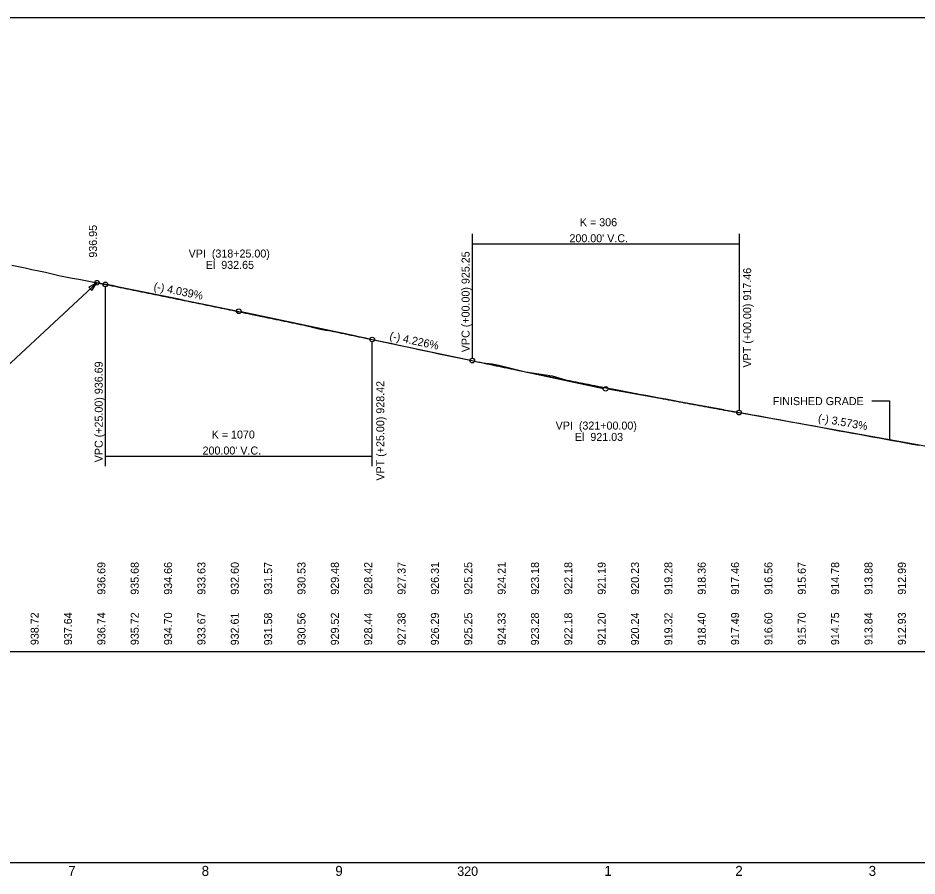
# Model space of a CAD drawing. Extents: x 4180 to 16997695, y 4 to 12629821.
# Drawn here: x 16984079 to 16984753, y 12626778 to 12627421 of the extents above; entities that cross this region are included whole.
import ezdxf

# ---------------------------------------------------------------- set-up
doc = ezdxf.new("R2010")
doc.units = 0
for name, color, linetype in [('Default', 7, 'Continuous'), ('RD_DDB_GradeTX', 7, 'Continuous'), ('RD_DDB_PI', 7, 'Continuous'), ('RD_DDB_PR_Tx', 7, 'Continuous'), ('RD_DDB_Profile_EX', 7, 'Continuous'), ('RD_DDB_Profile_PR', 7, 'Continuous'), ('RD_DDB_StaTX', 7, 'Continuous'), ('RD_DDB_StripGrade', 7, 'Continuous'), ('RD_DDB_StripGrade_PR', 7, 'Continuous'), ('RD_DDB_VCLbl', 7, 'Continuous'), ('RD_GPK_Profile_Cell', 7, 'Continuous'), ('RD_TX_Qty', 7, 'Continuous')]:
    doc.layers.add(name, color=color, linetype=linetype)

msp = doc.modelspace()

# ---------------------------------------------------------------- linework, layer by layer
at = {"layer": 'Default'}
msp.add_lwpolyline([(16983719.88, 12626945.95), (16985219.88, 12626945.95), (16985219.88, 12627420.95), (16983719.88, 12627420.95)], close=True, dxfattribs=at)
at = {"layer": 'RD_DDB_PI'}
for p, q in [((16984156.66, 12627218.86), (16984243.16, 12627201.39)), ((16984332.93, 12627182.43), (16984246.59, 12627200.68)), ((16984431.82, 12627161.54), (16984518.16, 12627143.29)), ((16984608.47, 12627127.1), (16984521.6, 12627142.62))]:
    msp.add_line(p, q, dxfattribs=at)
for centre in [(16984138.56, 12627222.51), (16984244.88, 12627201.04), (16984519.88, 12627142.93)]:
    msp.add_circle(centre, 1.75, dxfattribs=at)
at = {"layer": 'RD_DDB_PR_Tx'}
for p, q in [((16984719.29, 12627133.91), (16984732.71, 12627133.91)), ((16984732.71, 12627133.91), (16984732.71, 12627104.91))]:
    msp.add_line(p, q, dxfattribs=at)
at = {"layer": 'RD_DDB_Profile_EX'}
for points in [[(16984074.88, 12627235.61), (16984079.88, 12627234.57), (16984084.88, 12627233.52), (16984089.88, 12627232.46), (16984094.88, 12627231.4), (16984099.88, 12627230.35), (16984104.88, 12627229.19), (16984109.88, 12627227.88), (16984114.88, 12627226.94), (16984119.88, 12627226)], [(16984119.88, 12627226), (16984124.88, 12627225.06), (16984129.88, 12627224.12), (16984134.88, 12627223.19), (16984139.88, 12627222.33), (16984144.88, 12627221.49), (16984149.88, 12627220.55), (16984154.88, 12627219.34), (16984159.88, 12627218.35), (16984164.88, 12627217.37), (16984169.88, 12627216.38), (16984174.88, 12627215.38), (16984179.88, 12627214.36), (16984184.88, 12627213.34), (16984189.88, 12627212.32), (16984194.88, 12627211.31), (16984199.88, 12627210.29), (16984204.88, 12627209.26), (16984209.88, 12627208.23), (16984214.88, 12627207.19), (16984219.88, 12627206.13), (16984219.88, 12627206.13)], [(16984219.88, 12627206.13), (16984224.88, 12627205.07), (16984229.88, 12627204.02), (16984234.88, 12627202.96), (16984239.88, 12627201.9), (16984244.88, 12627200.85), (16984249.88, 12627199.8), (16984254.88, 12627198.75), (16984259.88, 12627197.7), (16984264.88, 12627196.68), (16984269.88, 12627195.67), (16984274.88, 12627194.66), (16984279.88, 12627193.65), (16984284.88, 12627192.64), (16984289.88, 12627191.62), (16984294.88, 12627190.61), (16984299.88, 12627189.26), (16984304.88, 12627187.83), (16984309.88, 12627186.84), (16984314.88, 12627186.45), (16984319.88, 12627185.39), (16984324.88, 12627184.32), (16984329.88, 12627183.25), (16984334.88, 12627182.16), (16984339.88, 12627181.07), (16984344.88, 12627179.99), (16984349.88, 12627178.93), (16984354.88, 12627177.88), (16984359.88, 12627176.82), (16984364.88, 12627175.76), (16984369.88, 12627174.68), (16984374.88, 12627173.61), (16984379.88, 12627172.53), (16984384.88, 12627171.43), (16984389.88, 12627170.34), (16984394.88, 12627169.24), (16984399.88, 12627168.18), (16984404.88, 12627167.14), (16984409.88, 12627166.11), (16984414.88, 12627165.08), (16984419.88, 12627164.04), (16984424.88, 12627162.99), (16984429.88, 12627162.21), (16984434.88, 12627161.57), (16984439.88, 12627160.72), (16984444.88, 12627159.42), (16984449.88, 12627158.12), (16984454.88, 12627156.82), (16984459.88, 12627155.61), (16984464.88, 12627154.89), (16984469.88, 12627154.18), (16984474.88, 12627153.46), (16984479.88, 12627152.61), (16984484.88, 12627151.18), (16984489.88, 12627149.7), (16984494.88, 12627148.7), (16984499.88, 12627147.72), (16984504.88, 12627146.74), (16984509.88, 12627145.76), (16984514.88, 12627144.77), (16984519.88, 12627143.78), (16984524.88, 12627142.8), (16984529.88, 12627141.81), (16984534.88, 12627140.87), (16984539.88, 12627139.92), (16984544.88, 12627138.98), (16984549.88, 12627138.06), (16984554.88, 12627137.14), (16984559.88, 12627136.23), (16984564.88, 12627135.31), (16984569.88, 12627134.37), (16984574.88, 12627133.42), (16984579.88, 12627132.48), (16984584.88, 12627131.56), (16984589.88, 12627130.66), (16984594.88, 12627129.77), (16984599.88, 12627128.87), (16984604.88, 12627127.95), (16984609.88, 12627127.03), (16984614.88, 12627126.11), (16984619.88, 12627125.23)], [(16984619.88, 12627125.23), (16984624.88, 12627124.37), (16984629.88, 12627123.52), (16984634.88, 12627122.64), (16984639.88, 12627121.71), (16984644.88, 12627120.77), (16984649.88, 12627119.84), (16984654.88, 12627118.93), (16984659.88, 12627118.05), (16984664.88, 12627117.17), (16984669.88, 12627116.29), (16984674.88, 12627115.37), (16984679.88, 12627114.41), (16984684.88, 12627113.45), (16984689.88, 12627112.48), (16984694.88, 12627111.53), (16984699.88, 12627110.63), (16984704.88, 12627109.73), (16984709.88, 12627108.83), (16984714.88, 12627107.92), (16984719.88, 12627107), (16984724.88, 12627106.07), (16984729.88, 12627105.14), (16984734.88, 12627104.23), (16984739.88, 12627103.34), (16984744.88, 12627102.44), (16984749.88, 12627101.54), (16984754.88, 12627100.66)]]:
    msp.add_lwpolyline(points, dxfattribs=at)
at = {"layer": 'RD_DDB_Profile_PR'}
for p, q in [((16984138.56, 12627222.51), (16984144.88, 12627221.24)), ((16984344.88, 12627179.91), (16984419.88, 12627164.06)), ((16984619.88, 12627125.07), (16984769.88, 12627098.27))]:
    msp.add_line(p, q, dxfattribs=at)
for points in [[(16984144.88, 12627221.24), (16984148.88, 12627220.43), (16984152.88, 12627219.62), (16984156.88, 12627218.81), (16984160.88, 12627218), (16984164.88, 12627217.19), (16984168.88, 12627216.38), (16984172.88, 12627215.56), (16984176.88, 12627214.75), (16984180.88, 12627213.94), (16984184.88, 12627213.12), (16984188.88, 12627212.31), (16984192.88, 12627211.49), (16984196.88, 12627210.67), (16984200.88, 12627209.85), (16984204.88, 12627209.04), (16984208.88, 12627208.22), (16984212.88, 12627207.4), (16984216.88, 12627206.57), (16984220.88, 12627205.75), (16984224.88, 12627204.93), (16984228.88, 12627204.11), (16984232.88, 12627203.28), (16984236.88, 12627202.46), (16984240.88, 12627201.63), (16984244.88, 12627200.81), (16984248.88, 12627199.98), (16984252.88, 12627199.15), (16984256.88, 12627198.32), (16984260.88, 12627197.49), (16984264.88, 12627196.66), (16984268.88, 12627195.83), (16984272.88, 12627195), (16984276.88, 12627194.17), (16984280.88, 12627193.34), (16984284.88, 12627192.5), (16984288.88, 12627191.67), (16984292.88, 12627190.83), (16984296.88, 12627190), (16984300.88, 12627189.16), (16984304.88, 12627188.32), (16984308.88, 12627187.49), (16984312.88, 12627186.65), (16984316.88, 12627185.81), (16984320.88, 12627184.97), (16984324.88, 12627184.13), (16984328.88, 12627183.28), (16984332.88, 12627182.44), (16984336.88, 12627181.6), (16984340.88, 12627180.75), (16984344.88, 12627179.91)], [(16984419.88, 12627164.06), (16984423.88, 12627163.22), (16984427.88, 12627162.37), (16984431.88, 12627161.54), (16984435.88, 12627160.7), (16984439.88, 12627159.87), (16984443.88, 12627159.04), (16984447.88, 12627158.21), (16984451.88, 12627157.38), (16984455.88, 12627156.56), (16984459.88, 12627155.74), (16984463.88, 12627154.92), (16984467.88, 12627154.1), (16984471.88, 12627153.29), (16984475.88, 12627152.48), (16984479.88, 12627151.68), (16984483.88, 12627150.87), (16984487.88, 12627150.07), (16984491.88, 12627149.27), (16984495.88, 12627148.47), (16984499.88, 12627147.68), (16984503.88, 12627146.89), (16984507.88, 12627146.1), (16984511.88, 12627145.31), (16984515.88, 12627144.53), (16984519.88, 12627143.75), (16984523.88, 12627142.97), (16984527.88, 12627142.19), (16984531.88, 12627141.42), (16984535.88, 12627140.65), (16984539.88, 12627139.88), (16984543.88, 12627139.11), (16984547.88, 12627138.35), (16984551.88, 12627137.59), (16984555.88, 12627136.83), (16984559.88, 12627136.08), (16984563.88, 12627135.32), (16984567.88, 12627134.57), (16984571.88, 12627133.83), (16984575.88, 12627133.08), (16984579.88, 12627132.34), (16984583.88, 12627131.6), (16984587.88, 12627130.87), (16984591.88, 12627130.13), (16984595.88, 12627129.4), (16984599.88, 12627128.67), (16984603.88, 12627127.94), (16984607.88, 12627127.22), (16984611.88, 12627126.5), (16984615.88, 12627125.78), (16984619.88, 12627125.07)]]:
    msp.add_spline(points, degree=3, dxfattribs=at)
at = {"layer": 'RD_DDB_VCLbl'}
for p, q in [((16984419.88, 12627259.06), (16984419.88, 12627165.81)), ((16984619.88, 12627259.06), (16984619.88, 12627126.82)), ((16984419.88, 12627251.56), (16984619.88, 12627251.56)), ((16984144.88, 12627084.91), (16984144.88, 12627219.49)), ((16984344.88, 12627084.91), (16984344.88, 12627178.16)), ((16984144.88, 12627092.41), (16984344.88, 12627092.41))]:
    msp.add_line(p, q, dxfattribs=at)
for centre in [(16984144.88, 12627221.24), (16984344.88, 12627179.91), (16984419.88, 12627164.06), (16984619.88, 12627125.07)]:
    msp.add_circle(centre, 1.75, dxfattribs=at)
at = {"layer": 'RD_GPK_Profile_Cell'}
msp.add_line((16972619.88, 12626787.79), (16997196.51, 12626787.79), dxfattribs=at)
at = {"layer": 'RD_TX_Qty'}
msp.add_lwpolyline([(16984015.09, 12627133.78), (16984042.07, 12627132.83), (16984138.56, 12627222.51)], dxfattribs=at)
msp.add_lwpolyline([(16984134.84, 12627216.58), (16984138.56, 12627222.51), (16984132.37, 12627219.24)], close=True, dxfattribs=at)

# ---------------------------------------------------------------- texts
at = {"layer": 'RD_DDB_GradeTX'}
for s, rotation, p in [('(-) 4.039%', 348.58138, (16984180.71, 12627217.06)), ('(-) 4.226%', 348.0679, (16984357.51, 12627179.95)), ('(-) 3.573%', 349.8722, (16984678.75, 12627118.36))]:
    msp.add_text(s, height=6, rotation=rotation, dxfattribs=at).set_placement(p)
at = {"layer": 'RD_DDB_PI'}
msp.add_text('936.95', height=6, rotation=90, dxfattribs=at).set_placement((16984138.56, 12627241.26))
for s, p in [('VPI  (318+25.00)', (16984207.29, 12627241.35)), ('El  932.65', (16984220.16, 12627232.85)), ('VPI  (321+00.00)', (16984482.4, 12627112.37)), ('El  921.03', (16984496.81, 12627103.87))]:
    msp.add_text(s, height=6, dxfattribs=at).set_placement(p)
at = {"layer": 'RD_DDB_PR_Tx'}
msp.add_text('FINISHED GRADE', height=6, dxfattribs=at).set_placement((16984645.11, 12627130.71))
at = {"layer": 'RD_DDB_StaTX'}
for s, height, p in [('7', 7.5, (16984117, 12626777.79)), ('8', 7.5, (16984217.03, 12626777.79)), ('9', 7.5, (16984317.23, 12626777.79)), ('320', 7, (16984408.63, 12626777.79)), ('1', 7.5, (16984518.87, 12626777.79)), ('2', 7.5, (16984617.03, 12626777.79)), ('3', 7.5, (16984717.03, 12626777.79))]:
    msp.add_text(s, height=height, dxfattribs=at).set_placement(p)
at = {"layer": 'RD_DDB_StripGrade'}
for s, p in [('938.72', (16984094.88, 12626950.8)), ('937.64', (16984119.88, 12626950.8)), ('936.74', (16984144.88, 12626950.8)), ('935.72', (16984169.88, 12626950.8)), ('934.70', (16984194.88, 12626950.8)), ('933.67', (16984219.88, 12626950.8)), ('932.61', (16984244.88, 12626950.63)), ('931.58', (16984269.88, 12626950.63)), ('930.56', (16984294.88, 12626950.63)), ('929.52', (16984319.88, 12626950.63)), ('928.44', (16984344.88, 12626950.63)), ('927.38', (16984369.88, 12626950.63)), ('926.29', (16984394.88, 12626950.63)), ('925.25', (16984419.88, 12626950.63)), ('924.33', (16984444.88, 12626950.63)), ('923.28', (16984469.88, 12626950.63)), ('922.18', (16984494.88, 12626950.63)), ('921.20', (16984519.88, 12626950.63)), ('920.24', (16984544.88, 12626950.63)), ('919.32', (16984569.88, 12626950.63)), ('918.40', (16984594.88, 12626950.63)), ('917.49', (16984619.88, 12626950.8)), ('916.60', (16984644.88, 12626950.8)), ('915.70', (16984669.88, 12626950.8)), ('914.75', (16984694.88, 12626950.8)), ('913.84', (16984719.88, 12626950.8)), ('912.93', (16984744.88, 12626950.8))]:
    msp.add_text(s, height=6, rotation=90, dxfattribs=at).set_placement(p)
at = {"layer": 'RD_DDB_StripGrade_PR'}
for s, p in [('936.69', (16984144.88, 12626988.58)), ('935.68', (16984169.88, 12626988.58)), ('934.66', (16984194.88, 12626988.58)), ('933.63', (16984219.88, 12626988.58)), ('932.60', (16984244.88, 12626988.58)), ('931.57', (16984269.88, 12626988.58)), ('930.53', (16984294.88, 12626988.58)), ('929.48', (16984319.88, 12626988.58)), ('928.42', (16984344.88, 12626988.58)), ('927.37', (16984369.88, 12626988.58)), ('926.31', (16984394.88, 12626988.58)), ('925.25', (16984419.88, 12626988.58)), ('924.21', (16984444.88, 12626988.58)), ('923.18', (16984469.88, 12626988.58)), ('922.18', (16984494.88, 12626988.58)), ('921.19', (16984519.88, 12626988.58)), ('920.23', (16984544.88, 12626988.58)), ('919.28', (16984569.88, 12626988.58)), ('918.36', (16984594.88, 12626988.58)), ('917.46', (16984619.88, 12626988.58)), ('916.56', (16984644.88, 12626988.58)), ('915.67', (16984669.88, 12626988.58)), ('914.78', (16984694.88, 12626988.58)), ('913.88', (16984719.88, 12626988.58)), ('912.99', (16984744.88, 12626988.58))]:
    msp.add_text(s, height=6, rotation=90, dxfattribs=at).set_placement(p)
at = {"layer": 'RD_DDB_VCLbl'}
for s, p in [('K = 306', (16984500.57, 12627264.81)), ("200.00' V.C.", (16984492.74, 12627252.81)), ('K = 1070', (16984224.56, 12627105.66)), ("200.00' V.C.", (16984217.74, 12627093.66))]:
    msp.add_text(s, height=6, dxfattribs=at).set_placement(p)
for s, p in [('VPC (+00.00) 925.25', (16984417.88, 12627170.39)), ('VPT (+00.00) 917.46', (16984628.94, 12627158.9)), ('VPC (+25.00) 936.69', (16984142.88, 12627087.86)), ('VPT (+25.00) 928.42', (16984353.94, 12627074.13))]:
    msp.add_text(s, height=6, rotation=90, dxfattribs=at).set_placement(p)

doc.saveas('drawing.dxf')
